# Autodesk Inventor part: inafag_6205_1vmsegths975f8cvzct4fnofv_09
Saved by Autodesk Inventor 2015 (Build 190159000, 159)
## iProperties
Company: TraceParts S.A.
Created: 2012-12
Part Number: inafag_6205_1vmsegths975f8cvzct4fnofv_09
Checked By: TraceParts S.A.
Catalog Web Link: www.traceparts.com
Document SubType Name: Modeling
Designer: TraceParts
Material: Generic
Density: 1 g/cm^3
Appearance: Default
Author: TraceParts
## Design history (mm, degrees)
feature "inafag_6205_1vmsegths975f8cvzct4fnofv"
body "Solid1"
